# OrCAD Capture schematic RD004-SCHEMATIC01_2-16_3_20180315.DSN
size A3
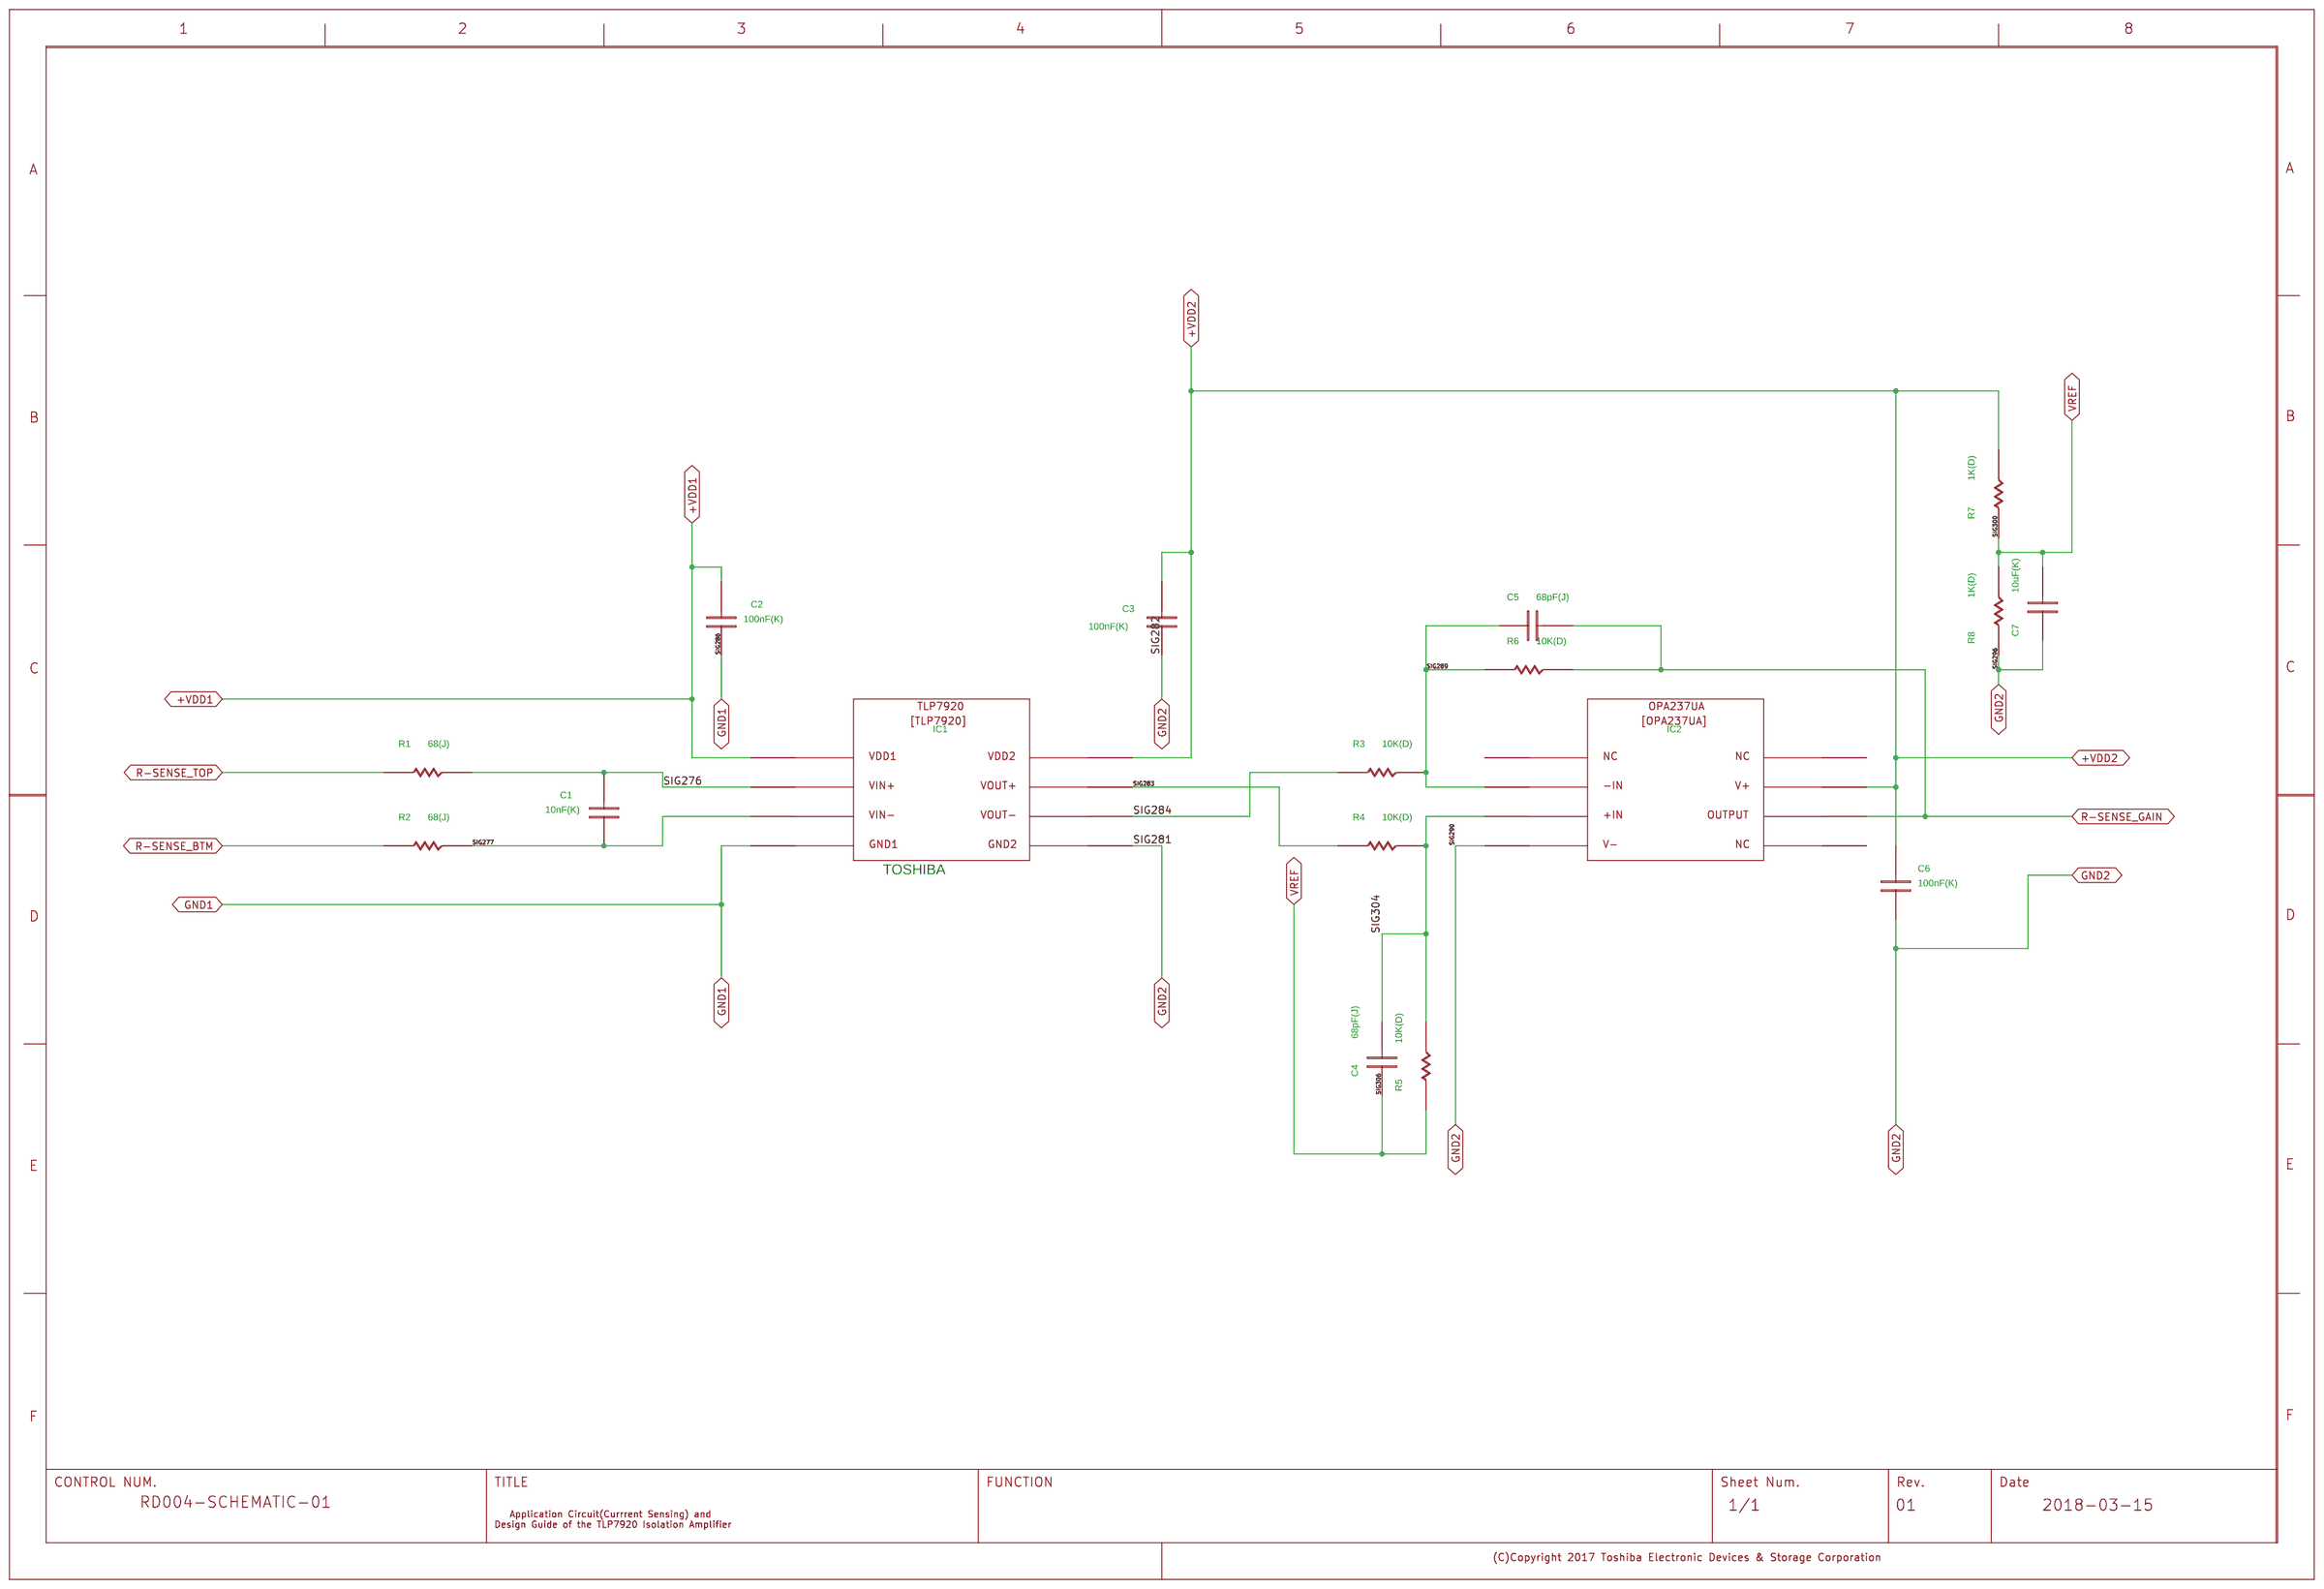
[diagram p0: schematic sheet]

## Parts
C1  C
C2  C
C3  C
C4  C
C5  C
C6  C
C7  C
IC1  S-TLP7920
IC2  S-OPA237UA
R1  R
R2  R
R3  R
R4  R
R5  R
R6  R
R7  R
R8  R
U?#1  WAKU_DEF100

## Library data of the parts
C1 = C: COMP: PRT_6; COMPONENTTYPE: 4; GCOUNT: 1; MAXGCOUNT: 1; SIZECODESMD: 1005; VAL1: 10nF(K); VAL2: 50V
C2 C3 C6 = C: COMP: PRT_7; COMPONENTTYPE: 4; GCOUNT: 1; MAXGCOUNT: 1; SIZECODESMD: 2012; VAL1: 100nF(K); VAL2: 25V
C4 C5 = C: COMP: PRT_8; COMPONENTTYPE: 4; GCOUNT: 1; MAXGCOUNT: 1; SIZECODESMD: 1608; VAL1: 68pF(J); VAL2: 100V
C7 = C: COMP: PRT_9; COMPONENTTYPE: 4; GCOUNT: 1; MAXGCOUNT: 1; SIZECODESMD: 2012; VAL1: 10uF(K); VAL2: 16V
IC1 = S-TLP7920: COMP: PRT_1; COMPONENTTYPE: 4; USERCOMPTEXT3: TOSHIBA
IC2 = S-OPA237UA: COMP: PRT_2; COMPONENTTYPE: 4; USERCOMPTEXT3: Texas Instruments
R1 R2 = R: COMP: PRT_3; COMPONENTTYPE: 4; GCOUNT: 1; MAXGCOUNT: 1; SIZECODESMD: 2012; VAL1: 68(J); VAL2: 250mW
R3-R6 = R: COMP: PRT_4; COMPONENTTYPE: 4; GCOUNT: 1; MAXGCOUNT: 1; SIZECODESMD: 2012; VAL1: 10K(D); VAL2: 250mW
R7 R8 = R: COMP: PRT_5; COMPONENTTYPE: 4; GCOUNT: 1; MAXGCOUNT: 1; SIZECODESMD: 2012; VAL1: 1K(D); VAL2: 250mW
U?#1 = WAKU_DEF100: COMPONENTTYPE: 2; DATE: 2018-03-15; DRAWINGNUMBER: RD004-SCHEMATIC-01; FUNCTION: POWER block; REVISION: 01; SHEETNUMBER: 1/1; TITLE: Application Circuit(Currrent Sensing) and / Design Guide of the TLP7920 Isolation Amplifier; UPDATEDATE: 2018/03/15; UPDATETIME: 09:59:54; UPDATEUSER: f1043010

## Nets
+VDD1: C2.2 IC1.1
+VDD2: C3.2 C6.2 IC1.8 IC2.7 R7.2
GND1: C2.1 IC1.4
GND2: C3.1 C6.1 C7.1 IC1.5 IC2.4 R8.1
R-SENSE_BTM: R2.1
R-SENSE_GAIN: C5.2 IC2.6 R6.2
R-SENSE_TOP: R1.1
SIG276: C1.2 IC1.2 R1.2
SIG277: C1.1 IC1.3 R2.2
SIG283: IC1.7 R4.1
SIG284: IC1.6 R3.1
SIG289: C5.1 IC2.2 R3.2 R6.1
SIG304: C4.2 IC2.3 R4.2 R5.2
VREF: C4.1 C7.2 R5.1 R7.1 R8.2

Not connected (* = marked no-connect by the designer): IC2 1 5 8
